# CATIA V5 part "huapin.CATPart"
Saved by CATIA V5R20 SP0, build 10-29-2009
Part number: 花瓶
Material "Chartreuse"
Bounding box of the stored display mesh (mm): x -46.425 to 46.425, y -46.425 to 83.431, z -2 to 203.161
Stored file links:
  C:\Users\LFZJ1125\Desktop\u'ei'iu'o.CATPart
  D:\catiaM\win_b64\startup\materials\Advanced_Materials.CATMaterial
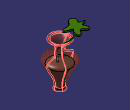
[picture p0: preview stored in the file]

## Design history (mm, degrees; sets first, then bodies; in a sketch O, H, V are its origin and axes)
Body1 (main body)
  Plane1: type Offset, RefPlane xy-plane, Offset 20
  Set1
    Plane2: type Offset, RefPlane xy-plane, Offset 40 {= Plane1.Offset * 2}
    Plane3: type Offset, RefPlane xy-plane, Offset 60 {= Plane1.Offset * 3}
  Plane4: type Offset, RefPlane Plane3, Offset 20
  Plane5: type Offset, RefPlane Plane4, Offset 20
  Set2
    Plane6: type Offset, RefPlane Plane4, Offset 40 {= Plane5.Offset * 2}
    Plane7: type Offset, RefPlane Plane4, Offset 60 {= Plane5.Offset * 3}
  Sketch1 on xy-plane, origin (0, 0, 0), H (1, 0, 0), V (0, 1, 0)
    circle A1 centre (0, 0) radius 15
    radius A1 = 15
  Sketch2 on Plane1, origin (0, 0, 20), H (1, 0, 0), V (0, 1, 0)
    circle A1 centre (0, 0) radius 17.5
    radius A1 = 17.5
  Sketch3 on Plane2, origin (0, 0, 40), H (1, 0, 0), V (0, 1, 0)
    circle A1 centre (0, 0) radius 23.9647
  Sketch4 on Plane3, origin (0, 0, 60), H (1, 0, 0), V (0, 1, 0)
    circle A1 centre (0, 0) radius 35
  Sketch5 on Plane4, origin (0, 0, 80), H (1, 0, 0), V (0, 1, 0)
    circle A1 centre (0, 0) radius 44.4249
  Sketch6 on Plane5, origin (0, 0, 100), H (1, 0, 0), V (0, 1, 0)
    circle A1 centre (0, 0) radius 15.8848
  Sketch7 on Plane6, origin (0, 0, 120), H (1, 0, 0), V (0, 1, 0)
    circle A1 centre (0, 0) radius 14.806
  Sketch8 on Plane7, origin (0, 0, 140), H (1, 0, 0), V (0, 1, 0)
    circle A1 centre (0, 0) radius 27.9419
  Loft1: solid, Sections (Sketch1; Sketch2; Sketch3; Sketch4; Sketch5; Sketch6; Sketch7; Sketch8)
  Sketch9 on Plane1, origin (0, 0, 20), H (1, 0, 0), V (0, 1, 0)
    reference intersected circle E1 centre (0, 0) radius 17.5 from face of Loft1
    reference intersected circle E2 centre (0, 0) radius 17.5 from face of Loft1
    distance E1 E2 = 35.0001 (reference)
  Sketch10 on xy-plane, origin (0, 0, 0), H (1, 0, 0), V (0, 1, 0)
    reference intersected circle E1 centre (0, 0) radius 15 from face of Loft1
    radius E1 = 15 (reference)
  Sketch11 on zx-plane, origin (0, 0, 0), H (-1, 0, 0), V (0, 0, 1)
    axis line L1 (0, 143.6404) -> (0, -9.5599)
    point P1 (0, 143.6404)
    line L2 (0, 69.6816) -> (34.7771, 69.6816)
    point P3 (0, 69.6816)
    point P4 (34.7771, 69.6816)
    spline S1 through (34.7771, 69.6816) (18.2257, 39.6359) (11.2741, 1.9961)
    line L3 (11.2741, 1.9961) -> (11.2741, 0)
    point P5 (11.2741, 1.9961)
    point P6 (11.2741, 0)
    line L4 (0, 0) -> (11.2741, 0)
    point P7 (34.7771, 69.6816)
    point P8 (11.2741, 1.9961)
    coincidence: P1 V, P3 L1, P7 P4, P8 P5, P6 H
    vertical: L1 V, L3 V
    horizontal: L2 H, L4 H
  Shell1: IntOffset 2, Face face of Loft1, ExtOffset 2
  Fillet1: radius 5, on face of Shell1
Body2, material "Chartreuse"
  Shaft1: profile Sketch11, axis Sketch11.L1, angle 360
  Sketch12 on yz-plane, origin (0, 0, 0), H (0, 1, 0), V (0, 0, 1)
    spline S1 through (0, 0) (0, 41.6054) (-9.4349, 93.7253) (45.1686, 166.9275) (54.5628, 196.794)
    point P1 (0, 0)
    point P2 (0, 41.6054)
    coincidence: P1 O, P2 V
  Plane8: type Normal, Curve Sketch12, RefPoint vertex of Sketch12
  Circle1: type CtrRad, Start 0, End 180, Radius 2.5, Center vertex of Sketch12, Support Plane8, FirstDirection (1, 0, 0)
  Rib1: profile Circle1, centre curve Sketch12
  Sketch13 on Plane8, origin (0, 8.8186, 198.8229), H (1, 0, 0), V (0, -0.999, 0.0443)
    spline S1 through (-20, -40) (-31.5211, -43.8061) (-15.7582, -50.881) (-20, -60.3143) (-20, -70.1407) (0, -60.3143) (6.7039, -67.7823) (15.3735, -74.4643) (20.4964, -60.3143) (11.8268, -47.7366) (24.0431, -43.8061) (35.0771, -35.1589) (6.7039, -28.477) (0, -19.4368) (-11.0294, -15.1132) (-20, -28.477) (-15.7582, -35.1589) (-20, -40)
    point P1 (0, -60.3143)
    point P2 (0, -19.4368)
    point P3 (-20, -40)
    point P4 (-20, -40)
    coincidence: P1 V, P2 V, P3 P4
  Pad1: profile Sketch13, direction (0, 0.0443, 0.999), length 5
